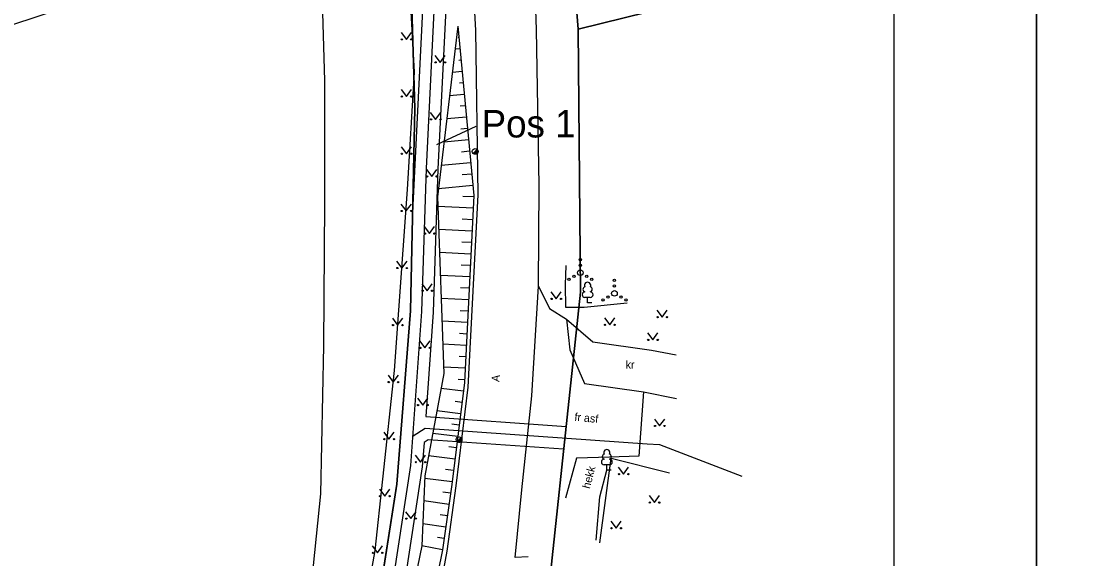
# Model space of a CAD drawing. Extents: x 554947 to 555436, y 6564938 to 6565792.
# Drawn here: x 555146.4 to 555239.7, y 6565248.3 to 6565295.3 of the extents above; entities that cross this region are included whole.
import ezdxf

# ---------------------------------------------------------------- set-up
doc = ezdxf.new("R2010")
doc.units = 0
for name, color, linetype in [('AED', 7, 'Continuous'), ('HALJASTUS', 7, 'Continuous'), ('KASUTUSALA', 7, 'Continuous'), ('KPKAABEL', 7, 'Continuous'), ('PIIR', 7, 'Continuous'), ('POST', 7, 'Continuous'), ('PR_SIDE', 7, 'Continuous'), ('PUU', 7, 'Continuous'), ('RELJEEF', 7, 'Continuous'), ('TEE', 7, 'Continuous'), ('VORMISTUS_1', 7, 'Continuous')]:
    doc.layers.add(name, color=color, linetype=linetype)

msp = doc.modelspace()

# ---------------------------------------------------------------- linework, layer by layer
at = {"layer": 'AED'}
for points in [[(555179.37, 6565300.078), (555180.242, 6565299.846), (555180.75, 6565290.874), (555180.137, 6565280.616), (555178.982, 6565264.788), (555177.984, 6565255.288), (555177.306, 6565249.05), (555173.486, 6565227.422), (555169.733, 6565212.423), (555163.779, 6565189.534), (555156.086, 6565161.758), (555151.428, 6565143.905), (555146.995, 6565125.891), (555142.273, 6565107.514), (555136.767, 6565086.759), (555131.214, 6565064.984), (555128.386, 6565056.617), (555127.142, 6565056.522)], [(555196.969, 6565249.734), (555197.967, 6565257.123), (555203.09, 6565255.853)], [(555196.662, 6565249.943), (555196.993, 6565253.757), (555197.595, 6565256.076)]]:
    msp.add_lwpolyline(points, dxfattribs=at)
at = {"layer": 'HALJASTUS'}
for p, q in [((555179.599, 6565294.336), (555180.062, 6565293.73)), ((555180.062, 6565293.73), (555180.508, 6565294.336)), ((555182.556, 6565292.327), (555183.019, 6565291.721)), ((555183.019, 6565291.721), (555183.465, 6565292.327)), ((555179.599, 6565289.336), (555180.062, 6565288.73)), ((555180.062, 6565288.73), (555180.508, 6565289.336)), ((555182.156, 6565287.343), (555182.62, 6565286.737)), ((555182.62, 6565286.737), (555183.065, 6565287.343)), ((555179.599, 6565284.336), (555180.062, 6565283.73)), ((555180.062, 6565283.73), (555180.508, 6565284.336)), ((555181.818, 6565282.356), (555182.281, 6565281.749)), ((555182.281, 6565281.749), (555182.727, 6565282.356)), ((555179.589, 6565279.337), (555180.053, 6565278.73)), ((555180.053, 6565278.73), (555180.498, 6565279.337)), ((555181.619, 6565277.36), (555182.083, 6565276.753)), ((555182.083, 6565276.753), (555182.528, 6565277.36)), ((555179.211, 6565274.351), (555179.675, 6565273.744)), ((555179.675, 6565273.744), (555180.12, 6565274.351)), ((555181.421, 6565272.364), (555181.884, 6565271.757)), ((555181.884, 6565271.757), (555182.33, 6565272.364)), ((555192.698, 6565271.648), (555193.162, 6565271.041)), ((555193.162, 6565271.041), (555193.607, 6565271.648)), ((555178.833, 6565269.365), (555179.297, 6565268.759)), ((555179.297, 6565268.759), (555179.742, 6565269.365)), ((555197.381, 6565269.385), (555197.844, 6565268.778)), ((555197.844, 6565268.778), (555198.29, 6565269.385)), ((555201.971, 6565270.059), (555202.435, 6565269.452)), ((555202.435, 6565269.452), (555202.88, 6565270.059)), ((555181.222, 6565267.368), (555181.686, 6565266.761)), ((555181.686, 6565266.761), (555182.131, 6565267.368)), ((555201.157, 6565268.064), (555201.62, 6565267.457)), ((555201.62, 6565267.457), (555202.066, 6565268.064)), ((555178.456, 6565264.38), (555178.919, 6565263.773)), ((555178.919, 6565263.773), (555179.365, 6565264.38)), ((555181.024, 6565262.371), (555181.487, 6565261.765)), ((555181.487, 6565261.765), (555181.933, 6565262.371)), ((555201.752, 6565260.544), (555202.215, 6565259.937)), ((555202.215, 6565259.937), (555202.66, 6565260.544)), ((555178.078, 6565259.394), (555178.541, 6565258.787)), ((555178.541, 6565258.787), (555178.987, 6565259.394)), ((555180.825, 6565257.375), (555181.289, 6565256.769)), ((555181.289, 6565256.769), (555181.734, 6565257.375)), ((555198.592, 6565256.328), (555199.055, 6565255.721)), ((555199.055, 6565255.721), (555199.501, 6565256.328)), ((555177.7, 6565254.408), (555178.163, 6565253.802)), ((555178.163, 6565253.802), (555178.609, 6565254.408)), ((555201.288, 6565253.846), (555201.752, 6565253.24)), ((555201.752, 6565253.24), (555202.197, 6565253.846)), ((555179.998, 6565252.444), (555180.462, 6565251.838)), ((555180.462, 6565251.838), (555180.907, 6565252.444)), ((555197.942, 6565251.606), (555198.405, 6565250.999)), ((555198.405, 6565250.999), (555198.851, 6565251.606)), ((555177.065, 6565249.457), (555177.528, 6565248.85)), ((555177.528, 6565248.85), (555177.974, 6565249.457))]:
    msp.add_line(p, q, dxfattribs=at)
msp.add_lwpolyline([(555199.375, 6565270.681), (555195.626, 6565270.307), (555194.015, 6565270.302), (555193.973, 6565272.287), (555194.036, 6565273.964)], dxfattribs=at)
for centre, radius in [((555179.661, 6565293.73), 0.055), ((555180.49, 6565293.73), 0.055), ((555182.618, 6565291.721), 0.055), ((555183.447, 6565291.721), 0.055), ((555179.661, 6565288.73), 0.055), ((555180.49, 6565288.73), 0.055), ((555182.219, 6565286.737), 0.055), ((555183.047, 6565286.737), 0.055), ((555179.661, 6565283.73), 0.055), ((555180.49, 6565283.73), 0.055), ((555181.88, 6565281.749), 0.055), ((555182.709, 6565281.749), 0.055), ((555179.652, 6565278.73), 0.055), ((555180.48, 6565278.73), 0.055), ((555181.682, 6565276.753), 0.055), ((555182.51, 6565276.753), 0.055), ((555195.276, 6565274.485), 0.1), ((555195.276, 6565273.985), 0.1), ((555179.274, 6565273.744), 0.055), ((555180.102, 6565273.744), 0.055), ((555194.711, 6565273.01), 0.1), ((555195.276, 6565273.335), 0.25), ((555195.841, 6565273.01), 0.1), ((555194.276, 6565272.76), 0.1), ((555196.276, 6565272.76), 0.1), ((555198.261, 6565272.678), 0.1), ((555198.261, 6565272.178), 0.1), ((555181.483, 6565271.757), 0.055), ((555182.312, 6565271.757), 0.055), ((555192.761, 6565271.041), 0.055), ((555193.589, 6565271.041), 0.055), ((555197.261, 6565270.953), 0.1), ((555197.696, 6565271.203), 0.1), ((555198.261, 6565271.528), 0.25), ((555198.826, 6565271.203), 0.1), ((555199.261, 6565270.953), 0.1), ((555202.033, 6565269.452), 0.055), ((555202.862, 6565269.452), 0.055), ((555178.896, 6565268.759), 0.055), ((555179.725, 6565268.759), 0.055), ((555197.443, 6565268.778), 0.055), ((555198.272, 6565268.778), 0.055), ((555201.219, 6565267.457), 0.055), ((555202.048, 6565267.457), 0.055), ((555181.285, 6565266.761), 0.055), ((555182.114, 6565266.761), 0.055), ((555178.518, 6565263.773), 0.055), ((555179.347, 6565263.773), 0.055), ((555181.086, 6565261.765), 0.055), ((555181.915, 6565261.765), 0.055), ((555201.814, 6565259.937), 0.055), ((555202.643, 6565259.937), 0.055), ((555178.14, 6565258.787), 0.055), ((555178.969, 6565258.787), 0.055), ((555180.888, 6565256.769), 0.055), ((555181.717, 6565256.769), 0.055), ((555198.654, 6565255.721), 0.055), ((555199.483, 6565255.721), 0.055), ((555177.762, 6565253.802), 0.055), ((555178.591, 6565253.802), 0.055), ((555201.351, 6565253.24), 0.055), ((555202.18, 6565253.24), 0.055), ((555180.061, 6565251.838), 0.055), ((555180.89, 6565251.838), 0.055), ((555198.004, 6565250.999), 0.055), ((555198.833, 6565250.999), 0.055), ((555177.127, 6565248.85), 0.055), ((555177.956, 6565248.85), 0.055)]:
    msp.add_circle(centre, radius, dxfattribs=at)
at = {"layer": 'KASUTUSALA'}
for points in [[(555129.194, 6565453.133), (555137.609, 6565433.851), (555144.751, 6565418.945), (555157.258, 6565394.612), (555165.015, 6565377.641), (555173.731, 6565356.879), (555178.352, 6565342.28), (555182.507, 6565323.462), (555183.157, 6565309.022), (555183.79, 6565302.23), (555182.806, 6565282.402), (555182.407, 6565269.888), (555181.762, 6565260.751), (555194.028, 6565259.888), (555193.816, 6565257.898), (555181.976, 6565258.731), (555181.603, 6565258.495), (555181.453, 6565256.368), (555178.899, 6565239.742)], [(555176.937, 6565240.135), (555179.22, 6565254.85), (555179.244, 6565255.16), (555179.541, 6565258.936), (555179.592, 6565259.587), (555180.41, 6565269.99), (555180.41, 6565269.99), (555180.41, 6565269.99), (555180.588, 6565278.069), (555181.785, 6565302.187), (555181.161, 6565308.884), (555180.517, 6565323.199), (555176.418, 6565341.761), (555171.852, 6565356.189), (555163.184, 6565376.838), (555155.458, 6565393.739), (555142.959, 6565418.055), (555135.79, 6565433.019), (555127.369, 6565452.314)]]:
    msp.add_lwpolyline(points, dxfattribs=at)
at = {"layer": 'KPKAABEL'}
msp.add_lwpolyline([(555126.894, 6565446.731), (555132.737, 6565435.388), (555136.366, 6565427.872), (555142.195, 6565415.637), (555145.001, 6565409.613), (555146.957, 6565405.365), (555152.799, 6565392.474), (555157.576, 6565380.671), (555161.529, 6565371.444), (555166.139, 6565359.889), (555169.783, 6565348.422), (555171.572, 6565337.25), (555172.523, 6565325.522), (555172.476, 6565313.268), (555172.511, 6565302.969), (555172.901, 6565290.135), (555172.887, 6565279.431), (555172.817, 6565266.938), (555172.536, 6565254.014), (555171.281, 6565241.464)], dxfattribs=at)
at = {"layer": 'PIIR'}
for points in [[(555393.069, 6565560.972), (555353.12, 6565523.87), (555343.14, 6565512.46), (555302.6, 6565539.71), (555242.37, 6565583.94), (555179.42, 6565586.32), (555138.98, 6565580.6), (555121.18, 6565602.26), (555116.17, 6565610.5), (555109.96, 6565624.83), (555093.56, 6565628.47), (555079.04, 6565618.4), (555074.13, 6565607.82), (555075.34, 6565593.24), (555091.74, 6565551.94), (555171.91, 6565394.64), (555191.35, 6565341.19), (555195.08, 6565294.61), (555195.28, 6565271.63), (555191.64, 6565237.48)], [(555153.01, 6565448.47), (555207.22, 6565406.57), (555216.83, 6565392.35), (555221.23, 6565376.06), (555206.9, 6565339.44), (555200.72, 6565310.3), (555205.15, 6565297.11), (555195.08, 6565294.61), (555191.35, 6565341.19), (555171.91, 6565394.64), (555091.74, 6565551.94)], [(555176.93, 6565240.09), (555179.22, 6565254.85), (555180.41, 6565269.99), (555180.8, 6565287.7), (555180.26, 6565306.43), (555178.11, 6565321.18), (555176.49, 6565331.05), (555172.72, 6565345.23), (555166.64, 6565360.5), (555160.07, 6565375.54), (555144.16, 6565410.6), (555124.27, 6565454.45)], [(555191.64, 6565237.48), (555195.28, 6565271.63), (555195.08, 6565294.61), (555205.15, 6565297.11), (555275.38, 6565300.17), (555292.52, 6565297.57), (555293.54, 6565286.23), (555256.63, 6565245.54)]]:
    msp.add_lwpolyline(points, dxfattribs=at)
msp.add_lwpolyline([(554962.55, 6565234.93), (555180.26, 6565306.43), (555180.8, 6565287.7), (555180.41, 6565269.99), (555179.22, 6565254.85), (555176.93, 6565240.09), (555172.7, 6565220.76), (555117.14, 6565008.97), (555108.27, 6564991.27)], close=True, dxfattribs=at)
at = {"layer": 'POST'}
for p, q in [((555185.903, 6565283.76), (555186.257, 6565284.113)), ((555184.495, 6565258.565), (555184.848, 6565258.919))]:
    msp.add_line(p, q, dxfattribs=at)
for centre in [(555186.08, 6565283.936), (555184.672, 6565258.742)]:
    msp.add_circle(centre, 0.25, dxfattribs=at)
for centre, radius, start, end in [((555186.08, 6565283.936), 0.225, 224.85406, 45.03563), ((555186.08, 6565283.936), 0.2, 224.84272, 45.04698), ((555186.08, 6565283.936), 0.175, 224.82813, 45.06157), ((555186.08, 6565283.936), 0.15, 224.80867, 45.08103), ((555186.08, 6565283.936), 0.125, 224.78144, 45.10826), ((555186.08, 6565283.936), 0.1, 224.74058, 45.14911), ((555186.08, 6565283.936), 0.075, 224.67249, 45.2172), ((555186.08, 6565283.936), 0.05, 224.53632, 45.35338), ((555186.08, 6565283.936), 0.025, 224.12776, 45.76193), ((555184.672, 6565258.742), 0.225, 224.85406, 45.03563), ((555184.672, 6565258.742), 0.2, 224.84272, 45.04698), ((555184.672, 6565258.742), 0.175, 224.82813, 45.06157), ((555184.672, 6565258.742), 0.15, 224.80867, 45.08103), ((555184.672, 6565258.742), 0.125, 224.78144, 45.10826), ((555184.672, 6565258.742), 0.1, 224.74058, 45.14911), ((555184.672, 6565258.742), 0.075, 224.67249, 45.2172), ((555184.672, 6565258.742), 0.05, 224.53632, 45.35338), ((555184.672, 6565258.742), 0.025, 224.12776, 45.76193)]:
    msp.add_arc(centre, radius, start, end, dxfattribs=at)
at = {"layer": 'PR_SIDE'}
for points in [[(555177.913, 6565239.906), (555180.459, 6565256.479), (555181.409, 6565269.94), (555181.807, 6565282.443), (555182.788, 6565302.209), (555182.159, 6565308.954), (555181.512, 6565323.331), (555177.385, 6565342.021), (555172.792, 6565356.535), (555164.1, 6565377.24), (555156.359, 6565394.176), (555143.855, 6565418.501), (555136.7, 6565433.435), (555128.282, 6565452.724)], [(555180.642, 6565259.069), (555181.718, 6565259.753), (555201.118, 6565258.387), (555202.213, 6565258.31), (555209.414, 6565255.559)]]:
    msp.add_lwpolyline(points, dxfattribs=at)
at = {"layer": 'PUU'}
for p, q in [((555196.151, 6565271.175), (555195.671, 6565271.175)), ((555195.911, 6565270.7), (555195.911, 6565271.175)), ((555196.291, 6565270.7), (555195.911, 6565270.7)), ((555197.835, 6565256.551), (555197.355, 6565256.551)), ((555197.595, 6565256.076), (555197.595, 6565256.551)), ((555197.975, 6565256.076), (555197.595, 6565256.076))]:
    msp.add_line(p, q, dxfattribs=at)
for centre, radius, start, end in [((555195.741, 6565271.872), 0.233, 109.02174, 253.14154), ((555195.911, 6565272.22), 0.277, 332.5799, 207.4201), ((555196.081, 6565271.872), 0.233, 286.85082, 70.98591), ((555195.673, 6565271.412), 0.238, 90.0016, 269.3953), ((555196.148, 6565271.412), 0.238, 270.6047, 89.9984), ((555197.425, 6565257.249), 0.233, 109.02174, 253.14154), ((555197.595, 6565257.596), 0.277, 332.5799, 207.4201), ((555197.765, 6565257.249), 0.233, 286.85082, 70.98591), ((555197.358, 6565256.789), 0.238, 90.0016, 269.3953), ((555197.833, 6565256.789), 0.238, 270.6047, 89.9984)]:
    msp.add_arc(centre, radius, start, end, dxfattribs=at)
at = {"layer": 'RELJEEF'}
for p, q in [((555184.659, 6565293.9), (555184.594, 6565293.894)), ((555184.752, 6565292.904), (555184.323, 6565292.864)), ((555184.845, 6565291.908), (555184.652, 6565291.89)), ((555184.938, 6565290.913), (555184.081, 6565290.833)), ((555185.031, 6565289.917), (555184.71, 6565289.887)), ((555185.125, 6565288.922), (555183.838, 6565288.801)), ((555185.218, 6565287.926), (555184.768, 6565287.884)), ((555185.311, 6565286.93), (555183.596, 6565286.77)), ((555185.404, 6565285.935), (555184.825, 6565285.88)), ((555185.497, 6565284.939), (555183.353, 6565284.738)), ((555185.591, 6565283.943), (555184.883, 6565283.877)), ((555185.684, 6565282.948), (555183.111, 6565282.707)), ((555185.777, 6565281.952), (555184.941, 6565281.874)), ((555185.87, 6565280.956), (555182.868, 6565280.675)), ((555185.947, 6565279.96), (555185.004, 6565280.007)), ((555185.898, 6565278.962), (555182.815, 6565279.114)), ((555185.848, 6565277.963), (555184.949, 6565278.007)), ((555185.799, 6565276.964), (555182.888, 6565277.108)), ((555185.749, 6565275.965), (555184.902, 6565276.007)), ((555185.699, 6565274.966), (555182.961, 6565275.102)), ((555185.65, 6565273.968), (555184.854, 6565274.007)), ((555185.6, 6565272.969), (555183.034, 6565273.096)), ((555185.551, 6565271.97), (555184.807, 6565272.007)), ((555185.501, 6565270.971), (555183.108, 6565271.09)), ((555185.452, 6565269.973), (555184.759, 6565270.007)), ((555185.402, 6565268.974), (555183.181, 6565269.084)), ((555185.353, 6565267.975), (555184.712, 6565268.007)), ((555185.303, 6565266.976), (555183.254, 6565267.078)), ((555185.254, 6565265.978), (555184.665, 6565266.007)), ((555185.204, 6565264.979), (555183.327, 6565265.072)), ((555185.154, 6565263.98), (555184.587, 6565264.008)), ((555185.049, 6565262.986), (555183.105, 6565263.225)), ((555184.928, 6565261.993), (555184.326, 6565262.067)), ((555184.806, 6565261.001), (555182.738, 6565261.255)), ((555184.684, 6565260.008), (555184.045, 6565260.087)), ((555184.562, 6565259.016), (555182.371, 6565259.285)), ((555184.44, 6565258.023), (555183.764, 6565258.106)), ((555184.318, 6565257.031), (555182.004, 6565257.315)), ((555184.196, 6565256.038), (555183.484, 6565256.126)), ((555184.074, 6565255.046), (555181.669, 6565255.341)), ((555183.794, 6565253.065), (555181.583, 6565253.383)), ((555183.937, 6565254.055), (555183.244, 6565254.155)), ((555183.652, 6565252.076), (555183.018, 6565252.167)), ((555183.51, 6565251.086), (555181.495, 6565251.375)), ((555183.367, 6565250.096), (555182.792, 6565250.179)), ((555183.225, 6565249.106), (555181.412, 6565249.474))]:
    msp.add_line(p, q, dxfattribs=at)
for points in [[(555184.566, 6565294.895), (555185.953, 6565280.072), (555185.143, 6565263.746), (555184.046, 6565254.819), (555183.226, 6565249.112), (555179.005, 6565228.311), (555174.467, 6565210.622), (555168.444, 6565187.982), (555160.102, 6565161.063), (555157.57, 6565157.837)], [(555184.566, 6565294.895), (555182.784, 6565279.965), (555183.347, 6565264.524), (555181.678, 6565255.565), (555181.412, 6565249.474), (555177.118, 6565228.691), (555172.906, 6565211.208), (555166.985, 6565188.606), (555158.553, 6565161.251), (555157.57, 6565157.837)]]:
    msp.add_lwpolyline(points, dxfattribs=at)
at = {"layer": 'TEE'}
for points in [[(555190.709, 6565248.513), (555189.563, 6565248.443), (555190.146, 6565254.361), (555191.039, 6565262.566), (555191.617, 6565272.16), (555191.671, 6565280.957), (555191.452, 6565294.595), (555190.904, 6565310.102), (555189.89, 6565321.445), (555187.257, 6565336.603), (555183.958, 6565348.1), (555179.78, 6565359.387), (555170.643, 6565380.205), (555162.823, 6565397.349), (555156.491, 6565411.721), (555150.933, 6565424.006), (555146.697, 6565433.416), (555136.695, 6565455.531)], [(555131.266, 6565453.894), (555141.635, 6565431.431), (555145.957, 6565421.634), (555151.76, 6565408.809), (555158.151, 6565395.066), (555165.93, 6565378.047), (555174.733, 6565357.312), (555178.536, 6565346.409), (555181.58, 6565335.07), (555184.177, 6565320.727), (555185.301, 6565309.018), (555186.111, 6565294.522), (555186.299, 6565280.132), (555185.431, 6565263.333), (555184.399, 6565254.7), (555183.594, 6565248.995), (555179.697, 6565227.862)], [(555191.617, 6565272.16), (555192.579, 6565270.195), (555194.074, 6565269.287), (555194.347, 6565266.594), (555195.639, 6565263.65), (555200.815, 6565262.91), (555200.393, 6565257.288), (555197.815, 6565257.202), (555194.937, 6565257.11), (555193.983, 6565253.619)], [(555194.074, 6565269.287), (555196.367, 6565267.28), (555201.508, 6565266.552), (555203.658, 6565266.143)], [(555200.815, 6565262.91), (555203.678, 6565262.346)]]:
    msp.add_lwpolyline(points, dxfattribs=at)
at = {"layer": 'VORMISTUS_1'}
msp.add_line((555182.728, 6565284.528), (555186.158, 6565286.137), dxfattribs=at)
for points in [[(555045.188, 6565158.913), (555235.188, 6565158.913), (555235.188, 6565433.913), (555045.188, 6565433.913)], [(555045.188, 6565433.913), (555235.188, 6565433.913), (555235.188, 6565158.913), (555045.188, 6565158.913)], [(555222.688, 6565184.913), (555057.688, 6565184.913), (555057.688, 6565394.913), (555222.688, 6565394.913)]]:
    msp.add_lwpolyline(points, close=True, dxfattribs=at)

# ---------------------------------------------------------------- texts
at = {"layer": 'HALJASTUS'}
msp.add_text('hekk', height=0.7, rotation=75.37115, dxfattribs=at).set_placement((555196.108, 6565254.407))
at = {"layer": 'TEE'}
for s, rotation, p in [('kr', 359.95437, (555199.239, 6565264.948)), ('A', 84.13165, (555188.192, 6565263.759)), ('fr asf', 354.68871, (555194.739, 6565260.393))]:
    msp.add_text(s, height=0.7, rotation=rotation, dxfattribs=at).set_placement(p)
at = {"layer": 'VORMISTUS_1'}
msp.add_text('Pos 1', height=2.4, dxfattribs=at).set_placement((555186.646, 6565285.154))

doc.saveas('drawing.dxf')
